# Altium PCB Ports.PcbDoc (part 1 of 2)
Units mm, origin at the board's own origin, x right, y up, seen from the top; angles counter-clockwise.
Board outline 100.96 x 99.82 mm, 2 copper layers (Top Layer, Bottom Layer); 116 components, 156 nets, 535 pads, 185 vias.
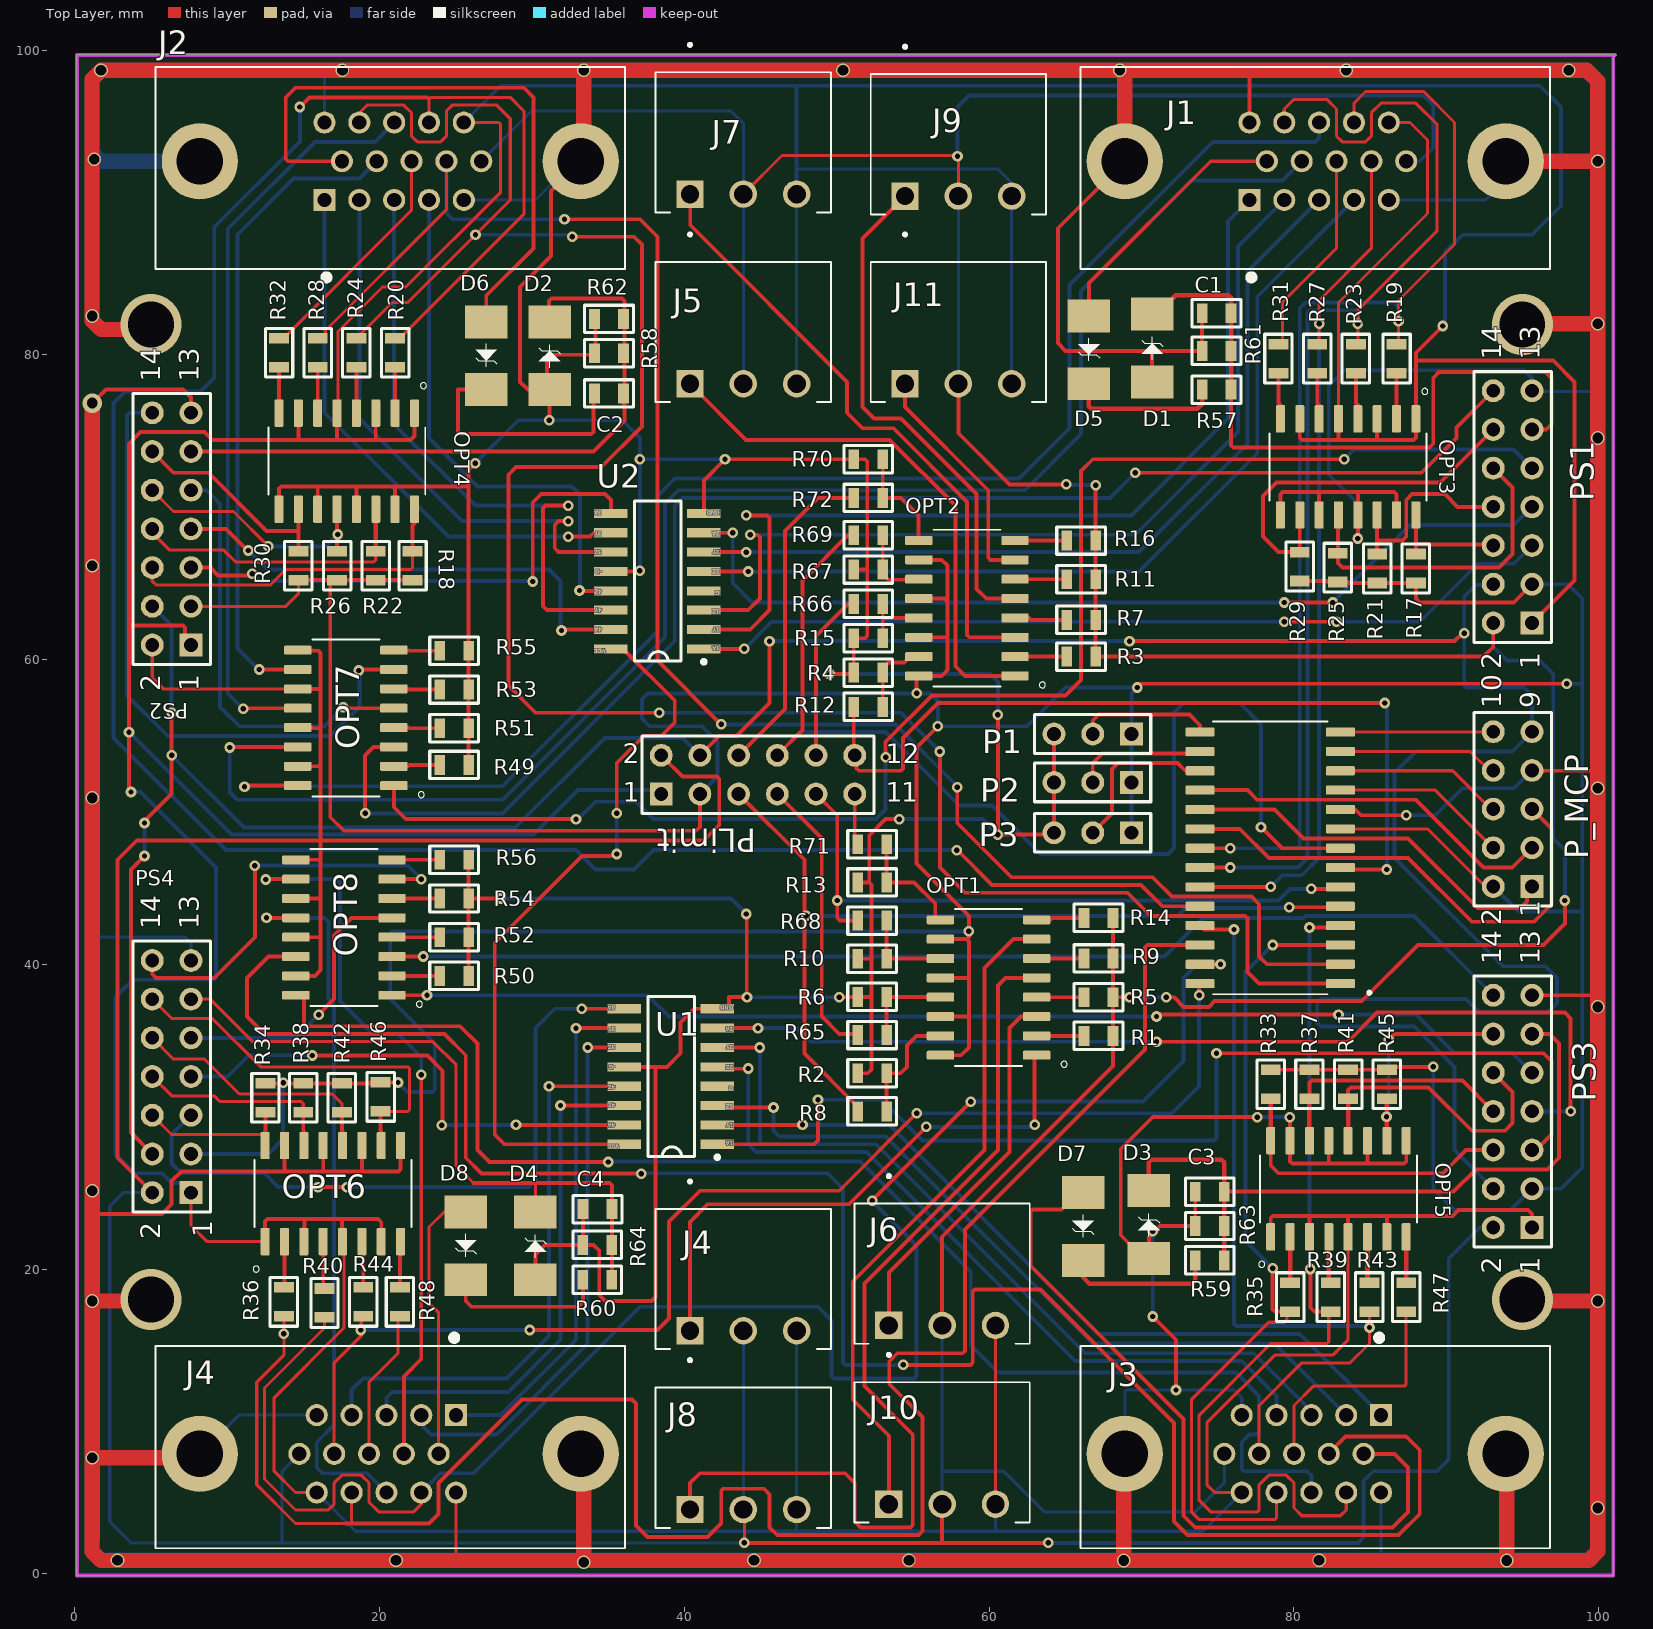
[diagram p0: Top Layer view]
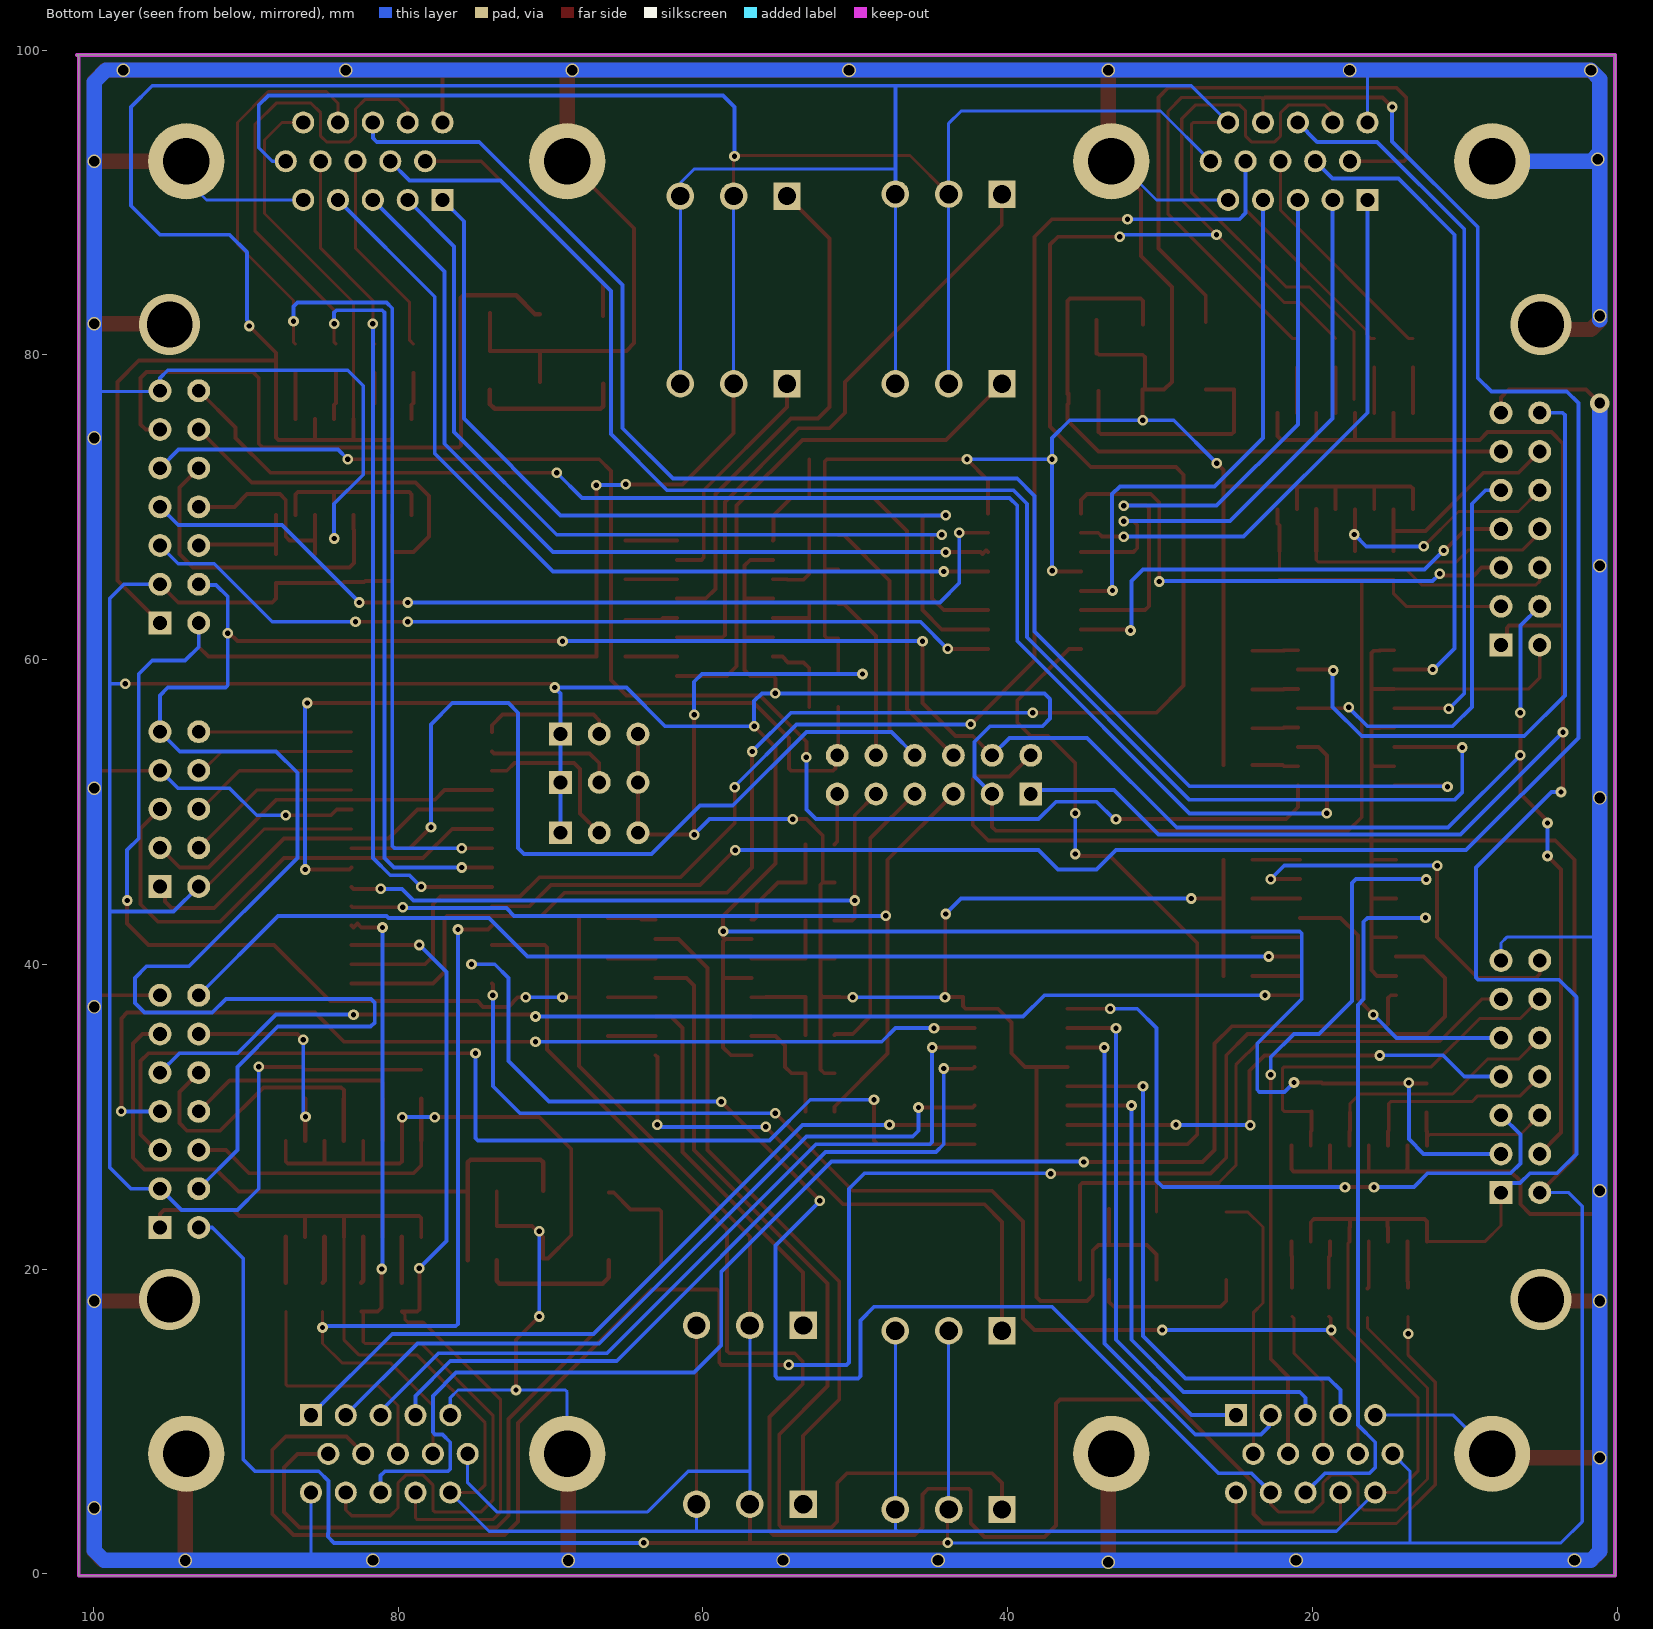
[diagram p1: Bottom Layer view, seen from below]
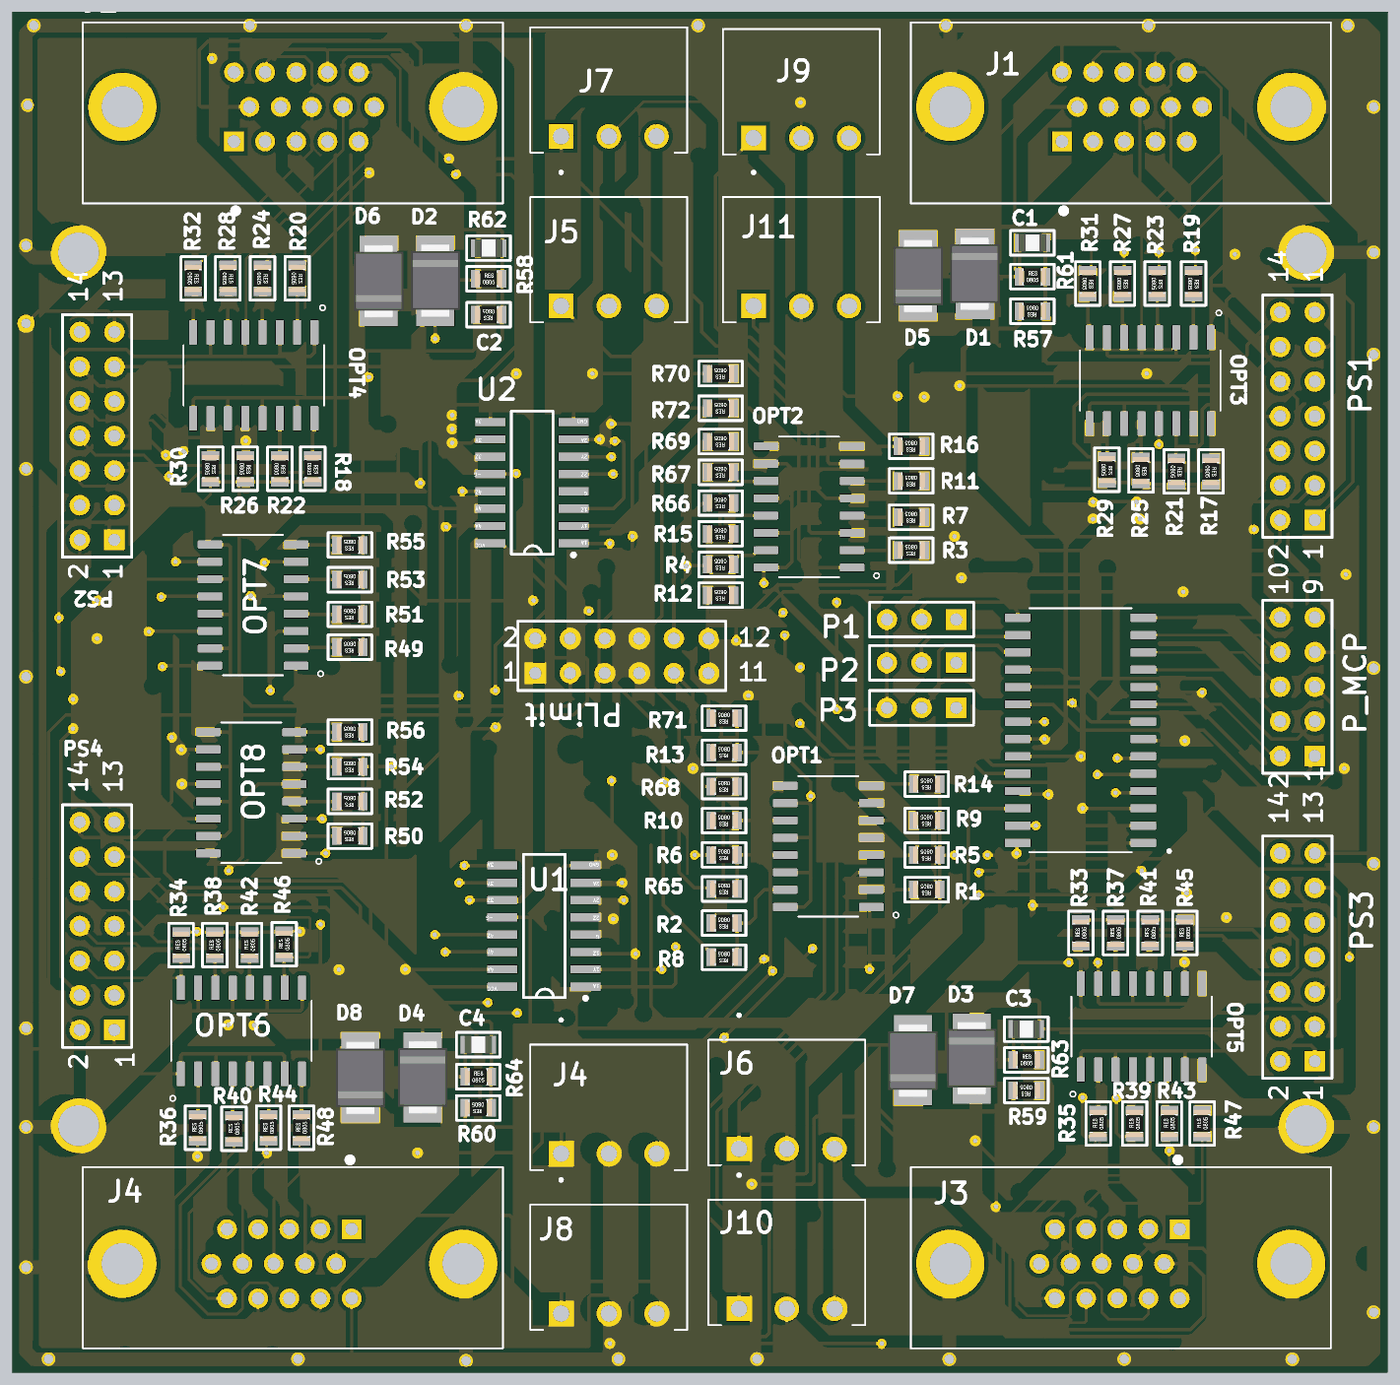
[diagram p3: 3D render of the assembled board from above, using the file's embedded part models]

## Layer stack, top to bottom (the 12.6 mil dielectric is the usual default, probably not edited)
Top Solder: solder mask 0.0102, Solder Resist, Dk 3.5
Top Layer: signal copper 0.0356
Dielectric 1: dielectric 0.32, FR-4, Dk 4.8
Bottom Layer: signal copper 0.0356
Bottom Solder: solder mask 0.0102, Solder Resist, Dk 3.5

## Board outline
0.127,-0.127 0.127,99.187 0.127,99.695 101.092,99.695 100.965,99.568 100.965,-0.127

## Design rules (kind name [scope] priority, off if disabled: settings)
AcuteAngle [All] p1: minimum=6.00000000000000E+0001 checktracksonly=TRUE
AssemblyTestPointUsage [(not InNetClass('NOTESTPOINTS'))] p1: allowmultiple=TRUE
AssemblyTestPointUsage AssemblyTestPointUsageN [InNetClass('NOTESTPOINTS')] p2: valid=2 allowmultiple=TRUE
AssemblyTestpoint [All] p1: testpointundercomponent=TRUE minsize=0.8 maxsize=2 preferedsize=1 minholesize=0 maxholesize=0.35 preferedholesize=0 testpointgrid=1.27 usegrid=FALSE gridoriginx=87.5 gridoriginy=62.5 gridtolerance=0 allowsidetop=TRUE minspacing=2.54 // Zollner
BoardOutlineClearance BoardCopperOutlineClearance [(OnLayer('Top Layer') OR OnLayer('Bottom Layer') )] p1: gap=0.5 ignorepadtopadclearanceinfootprint=FALSE except(1: Poly-OutlineEdge Region-OutlineEdge; 1.5: SMDPad-OutlineEdge THPad-OutlineEdge)
Clearance PadToViaClearance [IsVia and not IsComponentVia vs IsPad] p1: gap=0.025 ignorepadtopadclearanceinfootprint=TRUE
Clearance "Clearance (FAB)" [All] p2: gap=0.203 ignorepadtopadclearanceinfootprint=TRUE except(0.305: Arc-Poly Track-Poly SMDPad-Poly THPad-Poly Via-Poly Fill-Poly Poly-Poly)
ComponentClearance ComponentClearance_NetTie [((ObjectKind = 'Component') And (ComponentType = 'Net Tie')) Or (Footprint = 'StarPoint') Or (Footprint like 'NetTieVia*')] p1: gap=-3.81 collisioncheckmode=3 verticalgap=-3.81 showdistances=FALSE
ComponentClearance [All] p2: gap=0.254 collisioncheckmode=3 verticalgap=0.254 showdistances=FALSE
DiffPairsRouting [All] p1: maxlimit=1.27 minlimit=0.203 mostfreqgap=0.203 toplayer_minwidth=0.152 toplayer_maxwidth=2.54 toplayer_prefwidth=0.254 bottomlayer_minwidth=0.152 bottomlayer_maxwidth=2.54 bottomlayer_prefwidth=0.254 maxuncoupledlength=12.7
FabricationTestPointUsage [All] p1: valid=2 allowmultiple=FALSE
FabricationTestpoint [All] p1: side=3 testpointundercomponent=TRUE minsize=1.016 maxsize=2.54 preferedsize=1.524 minholesize=0 maxholesize=1.016 preferedholesize=0.813 testpointgrid=0.025 allowsidetop=TRUE allowsidebottom=TRUE usegrid=FALSE gridtolerance=0
HoleSize [All] p1: absolutevalues=TRUE maxlimit=6.35 minlimit=0.3 maxpercent=80.000 minpercent=20.000 // Zollner
HoleToHoleClearance HoleToHoleClearance_NetTieVia [InPadClass('NetTieVias') vs InPadClass('NetTieVias')] p1: gap=0 allowstackedmicrovias=TRUE
HoleToHoleClearance [All] p2: gap=0.25 allowstackedmicrovias=TRUE // Zollner
MinimumAnnularRing [All] p1: minimumring=0.15 // PCBWAY
MinimumSolderMaskSliver [All] p1: minsoldermaskwidth=0.2 // Zollner
PlaneClearance PlaneClearance_1 [All] p1: clearance=0.508
PlaneConnect [All] p1: pad.planeconnectstyle=Relief pad.reliefexpansion=0.508 pad.reliefentries=4 pad.reliefconductorwidth=0.254 pad.reliefairgap=0.254 via.planeconnectstyle=Direct via.reliefexpansion=0.508 via.reliefentries=4 via.reliefconductorwidth=0.254 via.reliefairgap=0.254
PolygonConnect [All] p1: thpad.connectstyle=Relief thpad.reliefconductorwidth=0.254 thpad.reliefentries=4 thpad.polygonreliefangle="90 Angle" thpad.airgapwidth=0.254 smdpad.connectstyle=Relief smdpad.reliefconductorwidth=0.254 smdpad.reliefentries=4 smdpad.polygonreliefangle="90 Angle" smdpad.airgapwidth=0.254 via.connectstyle=Direct via.reliefconductorwidth=0.254 via.reliefentries=4 via.polygonreliefangle="90 Angle" via.airgapwidth=0.254
RoutingVias [All] p1: holewidth=0.35 width=0.7 viastyle="Through Hole" minholewidth=0.3 minwidth=0.6 maxholewidth=1.27 maxwidth=1.27
SMDEntry [not IsTestpoint] p1: side=TRUE corner=TRUE anyangle=FALSE
SMDNeckDown [not IsTestpoint] p1: percent=90.000
SMDToCorner [All] p1: distance=10000
SMDToPlane [All] p1: distance=0
ShortCircuit [All vs not IsBoardCutoutRegion] p1: allowed=FALSE
SilkToSolderMaskClearance [IsPad] p1: minsilkscreentomaskgap=0.127 clearancetoexposedcopper=TRUE
SolderMaskExpansion [All] p1: expansion=0.05 istentingtop=FALSE // Zollner
SolderMaskExpansion SolderMaskExpansionToHoles [All] p2: expansion=0.1 istentingtop=FALSE soldermaskfromhole=TRUE // Zollner
UnRoutedNet [All] p1: checkbadconnections=TRUE
Width [All] p1: maxlimit=12.7 minlimit=0.203 preferedwidth=0.254
16 further rules are at their usual default settings.

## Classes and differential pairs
component class Ports: C1 C2 C3 C4 D1 D2 D3 D4 P1 P2 P3 P_MCP PLimit PS1 PS2 PS3 PS4 R57 R58 R59 R60 R61 R62 R63 R64
component class Optic: OPT3 OPT4 OPT5 OPT6 OPT7 OPT8 R17 R18 R19 R20 R21 R22 R23 R24 R25 R26 R27 R28 R29 R30 R31 R32 R33 R34 R35 R36 R37 R38 R39 R40 R41 R42 R43 R44 R45 R46 R47 R48 R49 R50 R51 R52 R53 R54 R55 R56
component class D-Sub15: J1 J2 J3 J4 J5 J6 J7 J8 J9 J10 J11 OPT1 OPT2 R1 R2 R3 R4 R5 R6 R7 R8 R9 R10 R11 R12 R13 R14 R15 R16 R65 R66 R67 R68 R69 R70 R71 R72 U1

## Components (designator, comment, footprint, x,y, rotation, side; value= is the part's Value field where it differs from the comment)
C1 "100nF" CAP0805 74.92,82.804 r0 top
C2 "100nF" CAP0805 35.049,82.423 r0 top
C3 "100nF" CAP0805 74.472,25.148 r0 top
C4 "100nF" CAP0805 34.29,24.003 r0 top
D1 "SS14" DO-214AA 70.704,82.677 r270 top
D2 "SS14" DO-214AA 31.153,82.169 r270 top
D3 "SS14" DO-214AA 70.485,25.146 r270 top
D4 "SS14" DO-214AA 30.226,23.749 r270 top
D5 "SS14" DO-214AA 66.548,78.105 r90 top
D6 "SS14" DO-214AA 26.998,77.724 r90 top
D7 "SS14" DO-214AA 66.167,20.574 r90 top
D8 "SS14" DO-214AA 25.654,19.304 r90 top
J1 "D-Sub15" D-Sub15 81.407,92.71 r180 top
J2 "D-Sub15" D-Sub15 20.701,92.71 r180 top
J3 "D-Sub15" D-Sub15 81.407,7.874 r0 top
J4 "D-Sub15" D-Sub15 20.701,7.874 r0 top
J4 "284512-3" TE_284512-3 43.871,15.951 r0 top
J5 "284512-3" TE_284512-3 43.871,78.105 r0 top
J6 "284512-3" TE_284512-3 56.921,16.301 r0 top
J7 "284512-3" TE_284512-3 43.871,90.551 r0 top
J8 "284512-3" TE_284512-3 43.871,4.222 r0 top
J9 "284512-3" TE_284512-3 57.983,90.424 r0 top
J10 "284512-3" TE_284512-3 56.921,4.572 r0 top
J11 "284512-3" TE_284512-3 57.983,78.105 r0 top
OPT1 "TLP281-4GB(F)" SOIC127P700X210-16N 59.964,38.481 r180 top
OPT2 "TLP281-4GB(F)" SOIC127P700X210-16N 58.547,63.373 r180 top
OPT3 "TLP281-4GB(F)" SOIC127P700X210-16N 83.566,72.647 r270 top
OPT4 "TLP281-4GB(F)" SOIC127P700X210-16N 17.843,73.025 r270 top
OPT5 "TLP281-4GB(F)" SOIC127P700X210-16N 82.931,25.27 r90 top
OPT6 "TLP281-4GB(F)" SOIC127P700X210-16N 16.932,24.957 r90 top
OPT7 "TLP281-4GB(F)" SOIC127P700X210-16N 17.783,56.175 r180 top
OPT8 "TLP281-4GB(F)" SOIC127P700X210-16N 17.656,42.418 r180 top
P1 "Header 3" HDR1X3 69.342,55.118 r180 top
P2 "Header 3" HDR1X3 69.342,51.943 r180 top
P3 "Header 3" HDR1X3 69.342,48.641 r180 top
P_MCP "Header 5X2" HDR2X5 95.631,45.11 r90 top
PLimit "Header 6X2" HDR2X6 38.481,51.181 r0 top
PS1 "Header 7X2" HDR2X7 95.631,62.407 r90 top
PS2 "Header 7X2" HDR2X7 7.62,60.96 r90 top
PS3 "Header 7X2" HDR2X7 95.631,22.733 r90 top
PS4 "Header 7X2" HDR2X7 7.62,25.019 r90 top
R1 "10k" Res0805 67.183,35.306 r180 top
R2 "10k" Res0805 52.324,32.857 r180 top
R3 "10k" Res0805 66.04,60.198 r180 top
R4 "10k" Res0805 52.07,59.15 r180 top
R5 "10k" Res0805 67.183,37.846 r180 top
R6 "10k" Res0805 52.324,37.864 r180 top
R7 "10k" Res0805 66.04,62.611 r180 top
R8 "10k" Res0805 52.324,30.353 r180 top
R9 "10k" Res0805 67.183,40.386 r180 top
R10 "10k" Res0805 52.324,40.368 r180 top
R11 "10k" Res0805 66.04,65.278 r180 top
R12 "10k" Res0805 52.07,56.896 r180 top
R13 "10k" Res0805 52.324,45.375 r180 top
R14 "10k" Res0805 67.183,43.053 r180 top
R15 "10k" Res0805 52.07,61.405 r180 top
R16 "10k" Res0805 66.04,67.818 r180 top
R17 "10k" Res0805 88.011,65.979 r270 top
R18 "10k" Res0805 22.162,66.167 r270 top
R19 "10k" Res0805 86.741,79.756 r270 top
R20 "10k" Res0805 21.018,80.137 r270 top
R21 "10k" Res0805 85.471,65.979 r270 top
R22 "10k" Res0805 19.748,66.167 r270 top
R23 "10k" Res0805 84.074,79.756 r270 top
R24 "10k" Res0805 18.479,80.137 r270 top
R25 "10k" Res0805 82.889,66.04 r270 top
R26 "10k" Res0805 17.209,66.167 r270 top
R27 "10k" Res0805 81.534,79.756 r270 top
R28 "10k" Res0805 15.938,80.137 r270 top
R29 "10k" Res0805 80.391,66.106 r270 top
R30 "10k" Res0805 14.668,66.167 r270 top
R31 "10k" Res0805 78.994,79.756 r270 top
R32 "10k" Res0805 13.399,80.137 r270 top
R33 "10k" Res0805 78.486,32.131 r90 top
R34 "10k" Res0805 12.507,31.242 r90 top
R35 "10k" Res0805 79.756,18.161 r90 top
R36 "10k" Res0805 13.716,17.848 r90 top
R37 "10k" Res0805 81.026,32.131 r90 top
R38 "10k" Res0805 14.986,31.242 r90 top
R39 "10k" Res0805 82.423,18.161 r90 top
R40 "10k" Res0805 16.383,17.78 r90 top
R41 "10k" Res0805 83.566,32.131 r90 top
R42 "10k" Res0805 17.526,31.242 r90 top
R43 "10k" Res0805 84.963,18.161 r90 top
R44 "10k" Res0805 18.923,17.848 r90 top
R45 "10k" Res0805 86.106,32.131 r90 top
R46 "10k" Res0805 20.066,31.303 r90 top
R47 "10k" Res0805 87.376,18.161 r90 top
R48 "10k" Res0805 21.336,17.848 r90 top
R49 "10k" Res0805 24.892,53.086 r180 top
R50 "10k" Res0805 24.892,39.243 r180 top
R51 "10k" Res0805 24.892,55.499 r180 top
R52 "10k" Res0805 24.892,41.783 r180 top
R53 "10k" Res0805 24.892,58.039 r180 top
R54 "10k" Res0805 24.892,44.323 r180 top
R55 "10k" Res0805 24.892,60.579 r180 top
R56 "10k" Res0805 24.892,46.863 r180 top
R57 "10k" Res0805 74.93,77.724 r180 top
R58 "10k" Res0805 35.059,77.47 r180 top
R59 "10k" Res0805 74.482,20.574 r180 top
R60 "10k" Res0805 34.29,19.304 r180 top
R61 "10k" Res0805 74.93,80.264 r0 top
R62 "10k" Res0805 35.059,80.104 r0 top
R63 "10k" Res0805 74.482,22.828 r0 top
R64 "10k" Res0805 34.29,21.59 r0 top
R65 "10k" Res0805 52.324,35.36 r180 top
R66 "10k" Res0805 52.07,63.659 r180 top
R67 "10k" Res0805 52.07,65.913 r180 top
R68 "10k" Res0805 52.324,42.872 r180 top
R69 "10k" Res0805 52.07,68.167 r180 top
R70 "10k" Res0805 52.07,73.152 r180 top
R71 "10k" Res0805 52.324,47.879 r180 top
R72 "10k" Res0805 52.07,70.612 r180 top
U1 "26LS31" 26LS31 37.914,33.576 r180 top
U2 "26LS31" 26LS31 37.029,66.088 r180 top
? "MCP23S17-E/SO" SOIC127P1030X265-28N 78.453,46.99 r180 top

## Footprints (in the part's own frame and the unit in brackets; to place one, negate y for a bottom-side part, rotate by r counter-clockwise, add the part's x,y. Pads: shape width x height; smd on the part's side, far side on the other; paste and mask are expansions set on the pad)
26LS31 [mm] "QFP, Ceramic; 100 Leads; Body 14 x 20 mm; Pitch 0.65 mm"
  rect 2.2x0.6 smd: 1(-4.25,5.382) 2(-4.25,4.112) 3(-4.25,2.842) 4(-4.25,1.572) 5(-4.25,0.302) 6(-4.25,-0.968) 7(-4.25,-2.238) 8(-4.25,-3.508) 9(1.85,-3.508) 10(1.85,-2.238) 11(1.85,-0.968) 12(1.85,0.302) 13(1.85,1.572) 14(1.85,2.842) 15(1.85,4.112) 16(1.85,5.382)
  silkscreen extent -4.37,-4.32 0.3,6.36
CAP0805 [mm] "0805 CAPACITOR FOOTPRINT"
  rect 0.7x1.3 smd: 1(-0.94,-0.065) 2(0.96,-0.065)
  silkscreen extent -1.59,-0.96 1.61,0.83, body extent -0.99,-0.72 1.01,0.59, height 0.73
D-Sub15 [mil]
  rect 57x57 hole 37: 1(170,100)
  round 57 hole 37: 2(80,100) 3(-10,100) 4(-100,100) 5(-190,100) 6(125,0) 7(35,0) 8(-55,0) 9(-145,0) 10(-235,0) 11(170,-100) 12(80,-100) 13(-10,-100) 14(-100,-100) 15(-190,-100)
  round 196.85 hole 120 unplated: ""(-492,0) ""(492,0)
  silkscreen extent -606,-244 606,308
DO-214AA [mil] "Diode, DO-214AA"
  rect 85x110 smd: 1(175,0) 2(0,0)
  silkscreen extent 59,-28 118,28, body extent -20,-71 193,71, height 90
HDR1X3 [mm] "Connector; Header; 3 Position"
  rect 1.5x1.5 hole 0.9: 1(0,0)
  round 1.5 hole 0.9: 2(2.54,0) 3(5.08,0)
  silkscreen extent -1.27,-1.27 6.35,1.27
HDR2X5 [mm] "Connector; Header; 5x2 Position"
  rect 1.5x1.5 hole 0.9: 1(0,0)
  round 1.5 hole 0.9: 2(0,2.54) 3(2.54,0) 4(2.54,2.54) 5(5.08,0) 6(5.08,2.54) 7(7.62,0) 8(7.62,2.54) 9(10.16,0) 10(10.16,2.54)
  silkscreen extent -1.27,-1.27 11.43,3.81
HDR2X6 [mm] "Connector; Header; 6x2 Position"
  rect 1.5x1.5 hole 0.9: 1(0,0)
  round 1.5 hole 0.9: 2(0,2.54) 3(2.54,0) 4(2.54,2.54) 5(5.08,0) 6(5.08,2.54) 7(7.62,0) 8(7.62,2.54) 9(10.16,0) 10(10.16,2.54) 11(12.7,0) 12(12.7,2.54)
  silkscreen extent -1.27,-1.27 13.97,3.81
HDR2X7 [mm] "Connector; Header; 7x2 Position"
  rect 1.5x1.5 hole 0.9: 1(0,0)
  round 1.5 hole 0.9: 2(0,2.54) 3(2.54,0) 4(2.54,2.54) 5(5.08,0) 6(5.08,2.54) 7(7.62,0) 8(7.62,2.54) 9(10.16,0) 10(10.16,2.54) 11(12.7,0) 12(12.7,2.54) 13(15.24,0) 14(15.24,2.54)
  silkscreen extent -1.27,-1.27 16.51,3.81
Res0805 [mm]
  rect 0.7x1.3 smd: 1(-0.95,0) 2(0.95,0)
  silkscreen extent -1.6,-0.9 1.6,0.9, body extent -1,-0.62 1,0.63, height 0.55
SOIC127P700X210-16N [mm]
  rrect25% 1.8x0.59 smd: 1(-3.155,4.445) 2(-3.155,3.175) 3(-3.155,1.905) 4(-3.155,0.635) 5(-3.155,-0.635) 6(-3.155,-1.905) 7(-3.155,-3.175) 8(-3.155,-4.445) 9(3.155,-4.445) 10(3.155,-3.175) 11(3.155,-1.905) 12(3.155,-0.635) 13(3.155,0.635) 14(3.155,1.905) 15(3.155,3.175) 16(3.155,4.445)
  silkscreen extent -5.15,-5.15 2.2,5.23
SOIC127P1030X265-28N [mm]
  rrect25% 1.9x0.6 smd: 1(-4.605,8.255) 2(-4.605,6.985) 3(-4.605,5.715) 4(-4.605,4.445) 5(-4.605,3.175) 6(-4.605,1.905) 7(-4.605,0.635) 8(-4.605,-0.635) 9(-4.605,-1.905) 10(-4.605,-3.175) 11(-4.605,-4.445) 12(-4.605,-5.715) 13(-4.605,-6.985) 14(-4.605,-8.255) 15(4.605,-8.255) 16(4.605,-6.985) 17(4.605,-5.715) 18(4.605,-4.445) 19(4.605,-3.175) 20(4.605,-1.905) 21(4.605,-0.635) 22(4.605,0.635) 23(4.605,1.905) 24(4.605,3.175) 25(4.605,4.445) 26(4.605,5.715) 27(4.605,6.985) 28(4.605,8.255)
  silkscreen extent -6.61,-8.95 3.75,8.95
TE_284512-3 [mm]
  rect 1.8x1.8 hole 1.2: 1(-3.5,0)
  round 1.8 hole 1.2: 2(0,0) 3(3.5,0)
  silkscreen extent -5.75,-1.2 5.75,9.9

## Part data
C1 C2 C3 C4: "100nF 50V,  X7R, ±10%, Ceramic Capacitor", Capacitance (Farads)=100n, Manufacturer=SAMSUNG, Manufacturer Part Number=CL21B104KBCNNNC, Package / Case="0805 (2012 Metric)", Tolerance=±10%
D1 D2 D3 D4 D5 D6 D7 D8: "1A 40V Schottky Diode", Current=1A, Manufacturer=PANJIT, Package=DO214AC
J1 J2 J3 J4: "15 Position D-Sub, High Density Receptacle, Female Sockets Connector", Package=None
J4 J5 J6 J7 J8 J9 J10 J11: "Pluggable terminal block; socket; male; angled; 3.5mm;", Package=None
OPT1 OPT2 OPT3 OPT4 OPT5 OPT6 OPT7 OPT8: "Optocoupler DC-IN 4-CH Transistor DC-OUT 16-Pin SOP", Package="SOP-16 Toshiba"
P1 P2 P3: "Header, 3-Pin"
P_MCP: "Header, 5-Pin, Dual row"
PLimit: "Header, 6-Pin, Dual row"
PS1 PS2 PS3 PS4: "Header, 7-Pin, Dual row"
R1 R2 R3 R4 R5 R6 R7 R8 R9 R10 R11 R12 R13 R14 R15 R16 R17 R18 R19 R20 R21 R22 R23 R24 R25 R26 R27 R28 R29 R30 R31 R32 R33 R34 R35 R36 R37 R38 R39 R40 R41 R42 R43 R44 R45 R46 R47 R48 R49 R50 R51 R52 R53 R54 R55 R56 R57 R58 R59 R60 R61 R62 R63 R64 R65 R66 R67 R68 R69 R70 R71 R72: library part "10k OHM", "RES 10k OHM 1/8W 5% 0805 SMD", Manufacturer=Royalohm, Manufacturer Part Number=0805S8F1002TDE, Package / Case="0805 (2012 Metric)", Power (Watts)="1/8W , 0.125W", Tolerance=±5%
U1 U2: "BUS DRIVER", PackageDocument=1994
?: "I/O Expander 16 SPI 10MHz 28-SOIC", Package="SOIC-28 Microchip"

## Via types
v1: diameter 0.7, hole 0.35, Top Layer to Bottom Layer, 151 vias
v2: diameter 0.9, hole 0.711, Top Layer to Bottom Layer, 29 vias
v3: diameter 4, hole 3, Top Layer to Bottom Layer, 4 vias
v4: diameter 1.27, hole 0.711, Top Layer to Bottom Layer, 1 vias

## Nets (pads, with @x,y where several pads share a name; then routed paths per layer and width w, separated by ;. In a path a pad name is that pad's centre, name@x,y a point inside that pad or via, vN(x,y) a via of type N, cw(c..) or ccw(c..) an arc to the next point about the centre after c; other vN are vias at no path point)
5V: P_MCP.9 PLimit.4 PS1.4 PS2.4 PS3.4 PS4.4 | length 216.9
  Top Layer w0.254: v1(4.572,47.117) 3.683,46.228 3.683,28.956 PS4.4@5.08,27.559 ; v1(4.572,49.276) 4.572,49.397 4.771,49.596 4.771,49.602 6.35,51.181 v1(6.35,56.515) ; PLimit.4@41.021,53.721 42.291,54.991 43.434,54.991 45.593,57.15 v1@45.593,61.087 ; v1(69.215,61.214) 90.557,61.214 91.065,61.722 v1(91.186,61.722)
  Bottom Layer w0.254: v1(4.572,47.117) v1(4.572,49.276) ; PS2.4@5.08,63.5 6.35,62.23 v1(6.35,56.515) ; v1(6.35,53.721) 11.1,48.971 28.905,48.971 34.798,54.864 39.878,54.864 PLimit.4@41.021,53.721 ; v1(45.593,61.214) v1(69.215,61.214) ; PS3.4@93.091,25.273 90.551,27.813 90.551,33.274 87.904,35.921 81.808,35.921 81.534,36.195 81.534,37.465 81.788,37.719 91.313,37.719 92.202,36.83 96.647,36.83 97.282,37.465 97.282,39.116 96.52,39.878 93.726,39.878 86.614,46.99 86.614,52.578 88.011,53.975 94.336,53.975 P_MCP.9@95.631,55.27 95.631,57.658 95.123,58.166 91.335,58.166 91.186,58.315 v1(91.186,61.722) 91.186,64.135 91.948,64.897 93.041,64.897 PS1.4@93.091,64.947
24V: J1.15 J2.15 J3.15 J4.3@47.371,15.951 J4.15 J5.3 J6.3 J7.3 J8.3 J9.3 J10.3 J11.3 OPT3.1 OPT3.3 OPT3.5 OPT3.7 OPT4.1 OPT4.3 OPT4.5 OPT4.7 OPT5.1 OPT5.3 OPT5.5 OPT5.7 OPT6.1 OPT6.3 OPT6.5 OPT6.7 PLimit.1 PS1.1 PS2.1 PS3.1 PS4.1 | length 549.1
  Top Layer w0.203: PS4.1@7.62,25.019 7.62,22.86 8.678,21.802 OPT6.1@12.487,21.802 ; J4.15@15.875,5.334 14.478,5.334 13.081,6.731 13.081,11.557 17.653,16.129 17.653,21.716 OPT6.5@17.567,21.802 ; 17.272,77.089 17.272,81.534 20.193,84.455 21.717,84.455 27.94,90.678 27.94,95.131 27.821,95.25 J2.15@25.527,95.25 ; J10.3@60.421,4.572 J6.3@60.421,16.301 ; J3.15@76.581,5.334 74.803,5.334 74.295,5.842 74.295,9.906 78.74,14.351 82.55,14.351 83.566,15.367 OPT5.5@83.566,22.115 ; OPT3.5@82.931,75.801 82.931,83.439 88.773,89.281 88.773,94.107 87.63,95.25 J1.15@86.233,95.25
  Top Layer w0.254: v1(3.683,51.308) 3.556,51.435 v1(3.556,55.245) 3.556,62.23 ; PS2.1@7.62,60.96 7.239,61.341 7.239,62.081 7.09,62.23 3.556,62.23 ; OPT6.1@12.487,21.802 12.487,23.133 12.636,23.282 15.081,23.282 ; OPT4.7@14.668,76.18 14.668,74.486 14.732,74.422 ; OPT6.3@15.027,21.802 15.027,22.728 15.081,22.782 15.081,23.282 ; OPT4.5@17.209,76.18 17.209,74.422 ; OPT6.5@17.567,21.802 17.567,22.728 17.526,22.769 17.526,23.282 ; OPT4.3@19.748,76.18 19.748,74.549 19.621,74.422 ; OPT6.7@20.107,21.802 20.107,23.073 19.898,23.282 17.526,23.282 ; OPT4.1@22.288,76.18 22.288,74.676 22.034,74.422 19.621,74.422 ; OPT5.1@78.486,22.115 78.486,23.346 78.635,23.495 81.1,23.495 ; OPT3.7@80.391,75.801 80.391,74.571 80.54,74.422 82.931,74.422 ; OPT5.3@81.026,22.115 81.026,23.421 81.1,23.495 ; OPT3.5@82.931,75.801 82.931,74.422 ; OPT5.5@83.566,22.115 83.566,23.495 ; OPT3.3@85.471,75.801 85.471,74.422 ; OPT5.7@86.106,22.115 86.106,23.495 ; v1(89.772,81.9) 88.011,80.139 88.011,79.629 ; PS3.1@95.631,22.733 95.631,23.622 95.377,23.876 90.805,23.876 90.424,23.495 86.106,23.495 ; PS1.1@95.631,62.407 98.425,65.201 98.425,78.232 97.028,79.629 88.011,79.629 ; 3.556,62.23 3.556,74.168 4.318,74.93 8.509,74.93 9.017,74.422 14.732,74.422 ; 14.732,74.422 17.209,74.422 ; 15.081,23.282 17.526,23.282 ; 17.209,74.422 19.621,74.422 ; 81.1,23.495 83.566,23.495 ; 82.931,74.422 85.471,74.422 ; 83.566,23.495 86.106,23.495 ; 85.471,74.422 87.862,74.422 88.011,74.571 OPT3.1@88.011,75.801 88.011,79.629
  Bottom Layer w0.203: J4.15@15.875,5.334 18.415,2.794 47.244,2.794 ; J2.15@25.527,95.25 27.94,97.663 46.482,97.663 ; J4.3@47.371,15.951 J8.3@47.371,4.222 47.371,2.921 47.244,2.794 ; J5.3@47.371,78.105 J7.3@47.371,90.551 ; 47.371,92.202 60.579,92.202 61.432,91.349 61.432,90.475 J9.3@61.483,90.424 J11.3@61.483,78.105 ; J10.3@60.421,4.572 60.421,2.794 ; J3.15@76.581,5.334 74.041,2.794 60.421,2.794 ; 47.244,2.794 60.421,2.794
  Bottom Layer w0.254: v1(3.556,55.245) 10.287,48.514 30.099,48.514 33.02,51.435 38.227,51.435 PLimit.1@38.481,51.181 ; v1(3.683,51.308) 4.318,51.308 9.271,46.355 9.271,39.138 9.122,38.989 3.81,38.989 2.667,37.846 2.667,27.559 3.937,26.289 5.715,26.289 6.362,25.642 6.997,25.642 PS4.1@7.62,25.019 ; 46.482,97.663 47.371,97.663 ; J7.3@47.371,90.551 47.371,92.202 47.371,97.663 ; v1@89.916,82.042 89.857,82.101 89.857,82.213 89.916,82.272 89.916,86.741 91.059,87.884 95.631,87.884 97.536,89.789 97.536,96.266 96.139,97.663 47.371,97.663
+3V3: ?.9 OPT1.10 OPT1.12 OPT1.14 OPT1.16 OPT2.10 OPT2.12 OPT2.14 OPT2.16 P1.1 P2.1 P3.1 P_MCP.2 PLimit.3 PS1.3 PS2.3 PS3.3 PS4.3 R17.2 R18.2 R21.2 R22.2 R25.2 R26.2 R29.2 R30.2 R33.2 R34.2 R37.2 R38.2 R41.2 R42.2 R45.2 R46.2 | length 368.1
  Top Layer w0.203: PS2.3@7.62,63.5 13.843,63.5 14.668,64.325 R30.2@14.668,65.217 ; ?.9@83.058,48.895 88.773,48.895 92.316,45.352 92.849,45.352 P_MCP.2@93.091,45.11
  Top Layer w0.254: R34.2@12.507,32.192 R38.2@14.986,32.192 R42.2@17.526,32.192 19.329,32.192 19.391,32.253 R46.2@20.066,32.253 20.741,32.253 20.746,32.258 v1@21.209,32.258 ; R30.2@14.668,65.217 R26.2@16.909,65.217 ; R18.2@22.162,65.217 R22.2@19.748,65.217 R26.2@17.209,65.217 R26.2@16.909,65.217 ; PLimit.3@41.021,51.181 41.021,49.022 40.767,48.768 17.653,48.768 16.764,49.657 16.764,65.072 R26.2@16.909,65.217 ; v1(55.245,57.785) 55.245,58.781 OPT2.16@55.392,58.928 56.896,58.928 57.277,59.309 57.277,61.468 ; OPT2.14@55.392,61.468 57.277,61.468 ; OPT2.12@55.392,64.008 57.087,64.008 57.277,63.817 ; OPT2.10@55.392,66.548 56.896,66.548 57.277,66.167 57.277,63.817 ; v1(56.642,55.626) 55.245,54.229 55.245,46.609 58.674,43.18 v1(58.674,42.164) 58.674,41.805 58.525,41.656 ; OPT1.16@56.809,34.036 58.166,34.036 58.674,34.544 58.674,36.576 ; OPT1.14@56.809,36.576 58.674,36.576 ; OPT1.12@56.809,39.116 58.674,39.116 ; OPT1.10@56.809,41.656 58.525,41.656 ; v1(69.723,58.166) 69.977,58.42 v1(97.917,58.42) ; R33.2@78.486,33.081 R37.2@81.026,33.081 R41.2@83.566,33.081 R45.2@86.106,33.081 86.299,33.274 v1(89.154,33.274) ; R29.2@80.391,65.156 82.164,65.156 82.23,65.09 R25.2@82.889,65.09 83.564,65.09 83.625,65.029 R21.2@85.471,65.029 R17.2@88.011,65.029 88.011,64.008 88.265,63.754 94.438,63.754 PS1.3@95.631,64.947 ; 57.277,61.468 57.277,63.817 ; 58.525,41.656 58.674,41.507 58.674,39.116 ; 58.674,36.576 58.674,39.116
  Bottom Layer w0.254: PS4.3@7.62,27.559 12.7,27.559 13.67,28.529 v1(13.67,32.236) ; v1(21.208,32.252) 21.837,31.623 23.473,31.623 23.622,31.772 23.622,34.798 20.701,37.719 20.701,42.015 20.85,42.164 v1(58.674,42.164) ; PLimit.3@41.021,51.181 41.021,51.308 41.148,51.308 42.164,52.324 42.164,54.61 41.148,55.626 37.719,55.626 37.211,56.134 37.211,57.404 37.592,57.785 56.134,57.785 56.642,57.277 v1(56.642,55.626) ; v1@56.515,55.626 62.484,55.626 65.024,58.166 v1(69.723,58.166) 69.342,57.785 69.342,56.239 P1.1@69.342,55.118 P2.1@69.342,51.943 P3.1@69.342,48.641 ; v1(89.154,33.274) 89.154,25.273 90.551,23.876 94.234,23.876 95.377,25.019 95.377,25.273 PS3.3@95.631,25.273 97.536,25.273 98.933,26.67 98.933,43.463 ; P_MCP.2@93.091,45.11 94.738,43.463 98.933,43.463 ; PS1.3@95.631,64.947 97.994,64.947 98.933,64.008 98.933,58.42 ; v1(97.917,58.42) 98.933,58.42 ; 98.933,43.463 98.933,58.42
+5V: U1.16 U2.16 | length 49.7
  Top Layer w0.254: U2.16@35.179,60.706 35.979,60.706 39.37,57.315 39.37,55.88 38.481,54.991 37.338,54.991 35.56,53.213 v1(35.56,49.911) v1@35.56,49.842 ; v1(35.56,47.244) 35.475,47.159 35.23,47.159 35.188,47.117 33.274,47.117 27.559,41.402 27.559,28.829 28.194,28.194 U1.16@36.064,28.194
  Bottom Layer w0.254: v1(35.56,47.244) v1(35.56,49.911)
A0: ?.15 P1.2 | length 8.8
  Top Layer w0.254: P1.2@66.802,55.118 66.802,56.007 67.183,56.388 73.152,56.388 73.848,55.692 ?.15@73.848,55.245
A1: ?.16 P2.2 | length 8.6
  Top Layer w0.254: P2.2@66.802,51.943 66.802,53.213 67.437,53.848 73.721,53.848 ?.16@73.848,53.975
A2: ?.17 P3.2 | length 10.9
  Top Layer w0.254: P3.2@66.802,48.641 68.072,49.911 68.072,52.832 68.453,53.213 72.365,53.213 72.873,52.705 ?.17@73.848,52.705
GND: ?.10 C1.1 C2.1 C3.1 C4.1 D1.1 D2.1 D3.1 D4.1 J1. J1.5 J1.11 J2. J2.5 J2.11 J3. J3.5 J3.11 J4. J4.5 J4.11 OPT3.9 OPT3.11 OPT3.13 OPT3.15 OPT4.9 OPT4.11 OPT4.13 OPT4.15 OPT5.9 OPT5.11 OPT5.13 OPT5.15 OPT6.9 OPT6.11 OPT6.13 OPT6.15 P1.3 P2.3 P3.3 P_MCP.7 PS1.13 PS2.13 PS3.13 PS4.13 R2.2 R4.2 R6.2 R10.2 R13.2 R15.2 R49.1 R50.1 R51.1 R52.1 R53.1 R54.1 R55.1 R56.1 R61.1 R62.1 R63.1 R64.1 R67.2 R70.2 U1.8 U1.12 U2.8 U2.12 | length 1361.2
  Top Layer w0.203: 25.019,0.873 J4.11@25.019,5.334
  Top Layer w0.254: 1.143,23.622 5.715,23.622 6.35,24.257 6.35,25.781 6.985,26.416 13.906,26.416 ; v4(1.143,76.835) 1.27,76.835 1.27,76.962 2.032,77.724 7.112,77.724 7.62,77.216 PS2.13@7.62,76.2 ; OPT4.9@13.399,69.87 13.399,71.225 13.547,71.374 15.938,71.374 ; OPT6.15@13.757,28.112 13.757,26.565 13.906,26.416 ; OPT4.11@15.938,69.87 15.938,71.374 ; OPT6.13@16.297,28.112 16.297,26.416 ; OPT4.13@18.479,69.87 18.479,71.3 18.404,71.374 ; OPT6.11@18.837,28.112 18.837,26.416 ; OPT4.15@21.018,69.87 21.018,71.225 20.87,71.374 ; OPT6.9@21.377,28.112 21.377,26.565 21.228,26.416 18.837,26.416 ; R50.1@25.842,39.243 R52.1@25.842,41.783 R54.1@25.842,44.323 ; R56.1@25.842,46.863 R54.1@25.842,44.323 ; R49.1@25.842,53.086 R51.1@25.842,55.499 R53.1@25.842,58.039 R55.1@25.842,60.579 25.842,71.374 ; v1(26.284,72.898) 25.842,72.456 25.842,71.374 ; v1(27.94,44.323) R54.1@25.842,44.323 ; D4.1@30.226,19.304 30.226,20.955 30.861,21.59 R64.1@33.34,21.59 ; v1(31.134,75.711) 31.153,75.73 D2.1@31.153,77.724 D2.1@30.988,77.724 ; J2.@33.198,92.71 31.242,90.754 31.242,86.487 29.223,84.468 29.223,78.232 29.731,77.724 D2.1@30.988,77.724 ; C4.1@33.35,23.938 33.35,22.275 33.34,22.265 R64.1@33.34,21.59 ; R62.1@34.109,80.104 34.015,80.01 31.137,80.01 30.988,79.861 D2.1@30.988,77.724 ; R62.1@34.163,80.104 C2.1@34.163,82.283 ; U2.12@35.179,65.786 v1@37.084,65.786 ; U1.12@36.064,33.274 38.1,33.274 ; U2.8@41.279,69.596 41.279,71.759 v1(42.672,73.152) R70.2@51.12,73.152 51.858,73.152 52.007,73.003 52.007,65.913 ; v1(44.069,43.307) 44.093,43.283 44.093,37.871 v1(44.117,37.847) 42.927,37.847 42.927,37.257 42.754,37.084 U1.8@42.164,37.084 40.64,37.084 39.751,36.195 39.751,34.163 38.862,33.274 38.1,33.274 ; v1(49.53,59.055) 51.025,59.055 R4.2@51.12,59.15 R15.2@51.12,61.405 51.858,61.405 52.007,61.553 52.007,65.913 ; v1(50.165,37.846) 50.98,37.846 50.999,37.864 R6.2@51.374,37.864 52.139,37.864 52.288,38.013 ; R67.2@51.12,65.913 52.007,65.913 ; R2.2@51.374,32.857 52.034,32.857 52.288,33.111 52.288,38.013 ; R10.2@51.374,40.368 52.27,40.368 52.288,40.386 ; R13.2@51.374,45.375 52.139,45.375 ; v1(54.102,49.53) 53.213,49.53 52.139,48.456 52.139,45.375 ; v1(60.579,56.388) v1(60.579,48.514) 60.581,48.512 64.133,48.512 P3.3@64.262,48.641 P2.3@64.262,51.943 P1.3@64.262,55.118 ; J1.@68.91,92.71 64.516,88.316 64.516,80.772 65.024,80.264 R61.1@73.98,80.264 C1.1@73.98,82.739 ; D1.1@70.704,78.232 70.704,80.264 ; v1(70.739,16.891) 72.263,15.367 v1(72.263,12.065) ; C3.1@73.532,25.083 R63.1@73.532,22.828 71.215,22.828 70.485,22.098 D3.1@70.485,20.701 70.168,20.701 68.644,22.225 68.644,27.877 70.739,29.972 v1(77.597,29.972) ; J1.11@77.089,95.25 77.089,98.679 ; OPT3.9@79.121,69.492 79.121,70.844 79.27,70.993 81.661,70.993 ; v1@79.756,29.972 OPT5.15@79.756,28.425 79.756,27.073 79.905,26.924 82.37,26.924 ; OPT3.11@81.661,69.492 81.661,70.993 ; OPT5.13@82.296,28.425 82.296,26.998 82.37,26.924 ; ?.10@83.058,50.165 84.033,50.165 84.414,49.784 v1(87.376,49.784) ; v1(84.201,67.945) OPT3.13@84.201,69.492 84.201,70.993 ; OPT5.11@84.836,28.425 84.836,26.924 ; OPT3.15@86.741,69.492 86.741,70.844 86.592,70.993 84.201,70.993 ; OPT5.9@87.376,28.425 87.376,27.073 87.227,26.924 84.836,26.924 ; PS3.13@95.631,37.973 99.949,37.973 ; P_MCP.7@95.631,52.73 95.656,52.705 99.949,52.705 ; 13.906,26.416 16.297,26.416 ; 15.938,71.374 18.404,71.374 ; 16.297,26.416 18.837,26.416 ; 18.404,71.374 20.87,71.374 ; 20.87,71.374 25.842,71.374 ; R64.1@33.34,21.59 34.036,21.59 34.417,21.209 34.417,18.288 34.798,17.907 37.846,17.907 38.1,18.161 38.1,33.274 ; 52.139,45.375 52.288,45.227 52.288,40.386 ; 52.288,38.013 52.288,40.386 ; 81.661,70.993 84.201,70.993 ; 82.37,26.924 84.836,26.924
  Top Layer w1: v4@1.143,76.708 v2(1.143,66.167) v2(1.143,50.927) v2(1.143,25.146) 1.143,23.622 v2(1.143,17.907) ; v3(5,18) 4.907,17.907 v2(1.143,17.907) ; v3(5,82) 4.661,81.661 1.713,81.661 1.127,82.247 1.127,98.093 v2(1.713,98.679) v2(17.557,98.679) v2(33.401,98.679) ; J4.@8.204,7.874 7.95,7.62 v2(1.143,7.62) ; J4.@33.198,7.874 33.401,7.671 v2@33.401,0.873 ; J2.@33.198,92.71 33.401,92.913 v2(33.401,98.679) ; J3.@68.91,7.874 68.834,7.798 v2(68.834,0.873) ; J1.@68.91,92.71 68.91,98.349 v2(68.58,98.679) ; J3.@93.904,7.874 93.98,7.798 v2(93.98,0.873) ; J1.@93.904,92.71 v2(99.949,92.71) ; v3(95,18) 95.093,17.907 v2(99.949,17.907) ; v3(95,82) 95.042,82.042 v2(99.949,82.042) ; v2(1.143,7.62) 1.143,2.303 1.127,2.287 1.127,1.459 1.713,0.873 25.019,0.873 v2@33.401,0.873 ; v2(1.143,7.62) v2(1.143,17.907) ; v2@33.401,0.873 v2(68.834,0.873) ; v2(33.401,98.679) v2(50.419,98.679) v2(68.58,98.679) ; v2(68.58,98.679) 77.089,98.679 v2(83.439,98.679) v2(98.044,98.679) 99.236,98.679 99.949,97.966 v2(99.949,92.71) ; v2(68.834,0.873) v2(93.98,0.873) ; v2(93.98,0.873) 99.363,0.873 99.949,1.459 v2(99.949,4.318) v2(99.949,17.907) ; v2(99.949,17.907) v2(99.949,37.211) 99.949,37.973 v2(99.949,51.562) 99.949,52.705 v2(99.949,74.549) v2(99.949,82.042) ; v2(99.949,82.042) v2(99.949,92.71)
  Bottom Layer w0.203: 1.143,41.783 7.239,41.783 7.62,41.402 PS4.13@7.62,40.259 ; J4.@8.204,7.874 10.744,10.414 J4.5@15.875,10.414 ; J2.11@16.383,95.25 16.383,98.695 ; J4.11@25.019,5.334 J4.11@25.146,5.207 ; J2.5@25.527,90.17 30.226,90.17 32.766,92.71 J2.@33.198,92.71 ; J3.@68.91,7.874 68.91,11.946 69.029,12.065 v1(72.263,12.065) 76.073,12.065 76.581,11.557 J3.5@76.581,10.414 ; 85.725,0.889 J3.11@85.725,5.334 ; J1.5@86.233,90.17 92.583,90.17 93.904,91.491 J1.@93.904,92.71 ; PS3.13@95.631,37.973 PS3.13@95.758,37.846 ; PS1.13@95.631,77.647 95.681,77.597 99.949,77.597
  Bottom Layer w0.254: v1(26.284,72.898) 29.097,75.711 v1(31.134,75.711) 35.922,75.711 37.082,74.551 v1(37.082,65.827) ; v1(27.94,44.323) 43.053,44.323 v1(44.069,43.307) ; v1(37.084,73.152) v1(42.672,73.152) ; v1@44.069,37.846 v1(50.165,37.846) ; v1(49.53,59.055) 60.071,59.055 60.579,58.547 v1(60.579,56.388) ; v1(54.102,49.53) 59.563,49.53 v1(60.579,48.514) v1@60.706,48.387 ; v1(70.739,16.891) v1(70.739,22.479) ; v1(77.597,29.972) v1@79.727,29.971 ; v1(84.201,67.945) 84.201,70.231 82.296,72.136 82.296,77.978 83.312,78.994 95.123,78.994 95.631,78.486 PS1.13@95.631,77.647 ; v1(87.376,49.784) 89.281,49.784 91.059,51.562 94.463,51.562 P_MCP.7@95.631,52.73 P_MCP.7@95.733,52.832
  Bottom Layer w1: v4(1.143,76.835) v2(1.143,66.167) v2(1.143,50.927) 1.143,41.783 v2(1.143,25.146) v2(1.143,17.907) v2(1.143,7.62) 1.143,1.475 1.729,0.889 v2(2.794,0.889) v2(21.082,0.889) 33.401,0.889 v2(44.577,0.889) v2(54.737,0.889) 68.834,0.889 v2(81.661,0.889) 85.725,0.889 93.98,0.889 99.314,0.889 99.949,1.524 v2(99.949,4.318) v2(99.949,17.907) v2(99.949,37.211) v2(99.949,51.562) v2(99.949,74.549) 99.949,77.597 v2(99.949,82.042) v2(99.949,92.71) 99.949,97.917 99.171,98.695 98.044,98.695 83.439,98.695 68.58,98.695 50.419,98.695 33.401,98.695 17.557,98.695 16.383,98.695 1.729,98.695 1.143,98.109 1.143,93.296 ; v2@1.143,82.296 v2(1.143,82.55) 1.143,92.837 1.143,93.296 ; J2.@8.204,92.71 1.729,92.71 1.143,93.296
  other v1: 79.727,29.971
  other v2: 33.401,0.762 1.27,92.837
GND24: J1.10 J2.10 J3.10 J4.2@43.871,15.951 J4.10 J5.2 J6.2 J7.2 J8.2 J9.2 J10.2 J11.2 OPT7.9 OPT7.11 OPT7.13 OPT7.15 OPT8.9 OPT8.11 OPT8.13 OPT8.15 PLimit.2 PS1.2 PS2.2 PS3.2 PS4.2 R1.1 R3.1 R5.1 R7.1 R9.1 R11.1 R14.1 R16.1 | length 552.7
  Top Layer w0.203: PS2.2@5.08,60.96 5.08,58.801 5.801,58.08 OPT7.11@14.628,58.08 ; J8.2@43.871,4.222 43.942,4.151 v1(43.942,2.032) ; J7.2@43.871,90.551 46.411,93.091 57.864,93.091 57.983,92.972 J9.2@57.983,90.424
  Top Layer w0.254: PS4.2@5.08,25.019 2.794,27.305 2.794,46.863 4.064,48.133 16.129,48.133 ; OPT8.15@14.501,39.243 15.748,39.243 16.129,39.624 16.129,41.783 ; OPT8.13@14.501,41.783 16.129,41.783 ; OPT8.11@14.501,44.323 16.055,44.323 16.129,44.249 ; OPT8.9@14.501,46.863 15.98,46.863 16.129,46.714 ; OPT7.15@14.628,53 15.98,53 16.129,53.149 ; OPT7.13@14.628,55.54 15.553,55.54 15.594,55.499 16.129,55.499 ; OPT7.11@14.628,58.08 16.014,58.08 16.129,57.965 ; OPT7.9@14.628,60.62 15.553,60.62 15.594,60.579 15.98,60.579 16.129,60.43 16.129,57.965 ; PLimit.2@38.481,53.721 38.608,53.721 38.608,53.594 39.878,52.324 42.142,52.324 42.291,52.175 42.291,49.149 41.275,48.133 16.256,48.133 ; v1(43.942,2.032) 56.921,2.032 ; J10.2@56.921,4.572 56.921,2.032 ; J6.2@56.921,16.301 56.921,22.123 68.133,33.335 R1.1@68.133,35.306 R5.1@68.133,37.846 ; J11.2@57.983,78.105 57.983,74.859 61.341,71.501 v1(65.073,71.501) ; v1(63.881,2.032) 56.921,2.032 ; v1(66.99,71.435) R16.1@66.99,67.818 R11.1@66.99,65.278 R7.1@66.99,62.611 R3.1@66.99,60.198 92.456,60.198 93.091,60.833 PS1.2@93.091,62.407 ; R14.1@68.133,43.053 R9.1@68.133,40.386 R5.1@68.133,37.846 ; v1(69.215,37.846) R5.1@68.133,37.846 ; v1(71.628,37.846) 72.136,37.846 72.771,37.211 74.422,37.211 74.803,37.592 84.455,37.592 88.138,41.275 96.393,41.275 97.79,42.672 v1(97.79,44.196) ; 16.129,41.783 16.129,44.249 ; 16.129,44.249 16.129,46.714 ; 16.129,46.714 16.129,48.133 ; 16.129,48.133 16.256,48.133 ; 16.129,53.149 16.129,48.26 16.256,48.133 ; 16.129,53.149 16.129,55.499 ; 16.129,55.499 16.129,57.965
  Bottom Layer w0.203: PS4.2@5.08,25.019 3.175,25.019 2.286,24.13 2.286,3.429 3.683,2.032 13.589,2.032 ; J4.10@14.732,7.874 13.589,6.731 13.589,2.032 ; J2.10@26.67,92.71 29.972,96.012 43.053,96.012 43.871,95.194 J7.2@43.871,90.551 J5.2@43.871,78.105 ; J8.2@43.871,4.572 J4.2@43.871,15.951 J4.2@43.871,16.301 ; v1(43.942,2.032) 13.589,2.032 ; J10.2@56.921,4.572 56.921,6.731 ; J6.2@56.921,16.301 56.921,6.731 ; J11.2@57.983,78.105 J9.2@57.983,90.424 ; J3.10@75.438,7.874 75.438,5.969 73.533,4.064 63.627,4.064 60.96,6.731 56.921,6.731
  Bottom Layer w0.254: v1(57.924,93.031) 57.924,96.278 58.674,97.028 88.519,97.028 89.154,96.393 89.154,93.599 88.265,92.71 J1.10@87.376,92.71 ; v1(63.881,2.032) 84.201,2.032 84.604,2.435 84.604,2.645 84.582,2.667 84.582,6.096 85.217,6.731 89.408,6.731 90.17,7.493 90.17,20.701 92.202,22.733 PS3.2@93.091,22.733 ; v1(65.073,71.501) 65.106,71.468 66.957,71.468 v1(66.99,71.435) ; v1(69.215,37.846) v1(71.628,37.846) ; PS1.2@93.091,62.407 92.964,62.28 93.091,62.153 93.091,60.833 93.98,59.944 96.139,59.944 97.028,59.055 97.028,48.26 97.79,47.498 v1(97.79,44.196)
MCP_CS: ?.11 P_MCP.4 | length 11.6
  Top Layer w0.203: ?.11@83.058,51.435 89.281,51.435 93.066,47.65 P_MCP.4@93.091,47.65
MCP_INTA: ?.20 P_MCP.5 | length 32.8
  Top Layer w0.254: ?.20@73.848,48.895 76.454,48.895 78.359,46.99 87.503,46.99 91.694,42.799 95.758,42.799 96.901,43.942 96.901,48.92 P_MCP.5@95.631,50.19
MCP_INTB: ?.19 P_MCP.1 | length 25.4
  Top Layer w0.254: ?.19@73.848,50.165 78.74,50.165 80.645,48.26 87.503,48.26 92.075,43.688 94.869,43.688 95.309,44.128 95.309,44.788 P_MCP.1@95.631,45.11
MCP_RESET: ?.18 P_MCP.3 | length 24.4
  Top Layer w0.254: ?.18@73.848,51.435 76.962,51.435 77.597,50.8 88.011,50.8 92.456,46.355 94.336,46.355 P_MCP.3@95.631,47.65
MCP_SCK: ?.12 P_MCP.6 | length 11.1
  Top Layer w0.203: ?.12@83.058,52.705 90.424,52.705 92.939,50.19 P_MCP.6@93.091,50.19
MCP_SI: ?.13 P_MCP.8 | length 10.5
  Top Layer w0.203: ?.13@83.058,53.975 91.567,53.975 92.812,52.73 P_MCP.8@93.091,52.73
MCP_SO: ?.14 P_MCP.10 | length 10
  Top Layer w0.203: ?.14@83.058,55.245 93.066,55.245 P_MCP.10@93.091,55.27
MCU_S1_DR: PS1.7 U2.7 | length 60.8
  Top Layer w0.254: U2.7@41.279,68.326 v1(43.18,68.326) ; v1(79.375,63.754) v1(82.55,63.754)
  Bottom Layer w0.254: v1(43.18,68.326) 43.18,65.024 44.45,63.754 v1(79.375,63.754) ; v1(82.55,63.754) 87.63,68.834 94.438,68.834 PS1.7@95.631,70.027
MCU_S1_PLS: PS1.5 U2.1 | length 57.2
  Top Layer w0.254: U2.1@41.279,60.706 v1(43.942,60.706) ; v1(79.375,62.484) v1(82.804,62.484)
  Bottom Layer w0.254: v1(43.942,60.706) 45.72,62.484 v1(79.375,62.484) ; v1(82.804,62.484) 88.265,62.484 92.075,66.294 94.438,66.294 95.554,67.41 95.554,67.487 PS1.5@95.631,67.487
MCU_S2_DR: PS2.7 U2.15 | length 32.1
  Top Layer w0.254: PS2.7@7.62,68.58 9.906,68.58 v1@11.366,67.12 ; v1(31.941,61.912) 32.004,61.976 U2.15@35.179,61.976
  Bottom Layer w0.254: v1(11.384,67.161) 12.632,65.913 31.115,65.913 31.877,65.151 v1@31.877,61.976
MCU_S2_PLS: PS2.5 U2.9 | length 34.4
  Top Layer w0.254: PS2.5@7.62,66.04 8.89,66.04 9.398,65.532 v1@11.557,65.532 ; v1(30.053,65.129) 30.053,70.312 30.607,70.866 34.798,70.866 35.179,70.485 U2.9@35.179,69.596
  Bottom Layer w0.254: v1(11.638,65.637) 11.706,65.637 11.706,65.569 12.124,65.151 v1@30.099,65.151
